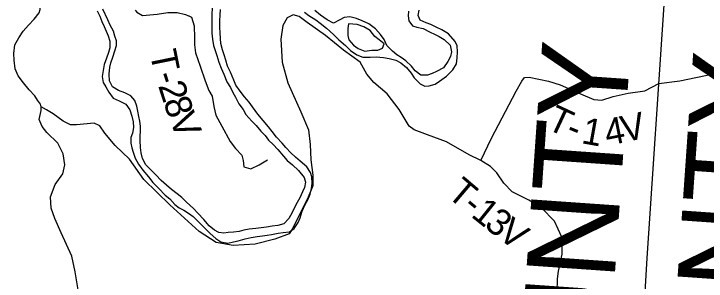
# Model space of a CAD drawing. Extents: x -15 to 405, y -40 to 87.
# Drawn here: x 26.119 to 27.6, y -28.766 to -28.194 of the extents above; entities that cross this region are included whole.
import ezdxf

# ---------------------------------------------------------------- set-up
doc = ezdxf.new("R2010")
doc.units = 0
for name, color, linetype in [('GM_P_State_Alignment', 7, 'Continuous'), ('GM_P_State_Location', 7, 'Continuous'), ('GM_X_Minor_River', 7, 'Continuous'), ('GM_X_Rail_Line', 7, 'Continuous'), ('GM_X_Township_Road', 7, 'Continuous'), ('GM_X_Township_Text', 7, 'Continuous')]:
    doc.layers.add(name, color=color, linetype=linetype)

msp = doc.modelspace()

# ---------------------------------------------------------------- linework, layer by layer
at = {"layer": 'GM_P_State_Location'}
for points in [[(26.3783, -28.1861), (26.3821, -28.1901), (26.394, -28.1971), (26.4255, -28.1944), (26.4482, -28.1908), (26.4683, -28.1911), (26.4863, -28.1956), (26.4927, -28.1984)], [(27.2809, -28.7893), (27.2815, -28.7612), (27.2838, -28.7445), (27.292, -28.7085), (27.2911, -28.6721), (27.2751, -28.6373), (27.2473, -28.6093), (27.2207, -28.5927), (27.185, -28.5749), (27.1668, -28.556), (27.1523, -28.5344), (27.1382, -28.5208), (27.1177, -28.5076), (27.0927, -28.4959), (27.044, -28.468), (27.0038, -28.4525), (26.9754, -28.4424), (26.9643, -28.4341), (26.943, -28.3985), (26.9175, -28.3648), (26.889, -28.3406), (26.8741, -28.3228), (26.86, -28.2975), (26.8239, -28.2714), (26.7852, -28.24), (26.7464, -28.2121), (26.7293, -28.1996), (26.7164, -28.1958), (26.7036, -28.2027), (26.6941, -28.2186), (26.6901, -28.2478), (26.6925, -28.2971), (26.7048, -28.3418), (26.7327, -28.4039), (26.7495, -28.4422), (26.753, -28.4736), (26.7542, -28.5062), (26.7585, -28.5392), (26.7586, -28.562), (26.7484, -28.5862), (26.7157, -28.6527), (26.7078, -28.6648), (26.6775, -28.6759), (26.6354, -28.687), (26.5881, -28.6898), (26.5517, -28.6834), (26.5156, -28.6596), (26.4525, -28.6025), (26.3973, -28.5484), (26.3661, -28.5049), (26.3357, -28.4754), (26.3136, -28.4493), (26.3029, -28.4334), (26.2908, -28.4278), (26.2529, -28.4313), (26.24, -28.4317), (26.2245, -28.4234), (26.2028, -28.4075), (26.1891, -28.3992), (26.1777, -28.3928)], [(26.4927, -28.1984), (26.4929, -28.1985), (26.4986, -28.201), (26.5048, -28.2198), (26.505, -28.2453), (26.505, -28.2605), (26.5073, -28.2771), (26.5172, -28.3061), (26.5282, -28.3374), (26.5359, -28.3577), (26.5431, -28.3701), (26.547, -28.3924), (26.5513, -28.4105), (26.564, -28.4345), (26.5819, -28.4668), (26.5933, -28.4817), (26.6066, -28.4966), (26.6091, -28.5075), (26.6106, -28.5216), (26.6259, -28.5254), (26.644, -28.5169), (26.6612, -28.5066)], [(27.4986, -28.3432), (27.5435, -28.3374), (27.6152, -28.3221), (27.7235, -28.324), (27.7512, -28.341), (27.7998, -28.3471), (27.8689, -28.3524), (27.9475, -28.3459), (27.9863, -28.3405)], [(27.1177, -28.5076), (27.1407, -28.4602), (27.1934, -28.3596), (27.2054, -28.3383), (27.2115, -28.3299), (27.221, -28.3292), (27.2623, -28.3382), (27.2877, -28.3457), (27.331, -28.3653), (27.3595, -28.377), (27.3765, -28.3788), (27.4008, -28.3708), (27.4326, -28.3639), (27.4686, -28.3589), (27.4986, -28.3432)]]:
    msp.add_lwpolyline(points, dxfattribs=at)
at = {"layer": 'GM_X_Rail_Line'}
for p, q in [((27.4737, -28.7166), (27.5098, -28.1749)), ((27.4349, -29.3708), (27.4737, -28.7166))]:
    msp.add_line(p, q, dxfattribs=at)
at = {"layer": 'GM_X_Township_Road'}
for points in [[(26.2969, -28.1874), (26.3026, -28.1988), (26.3075, -28.2102), (26.3124, -28.2212), (26.3162, -28.2311), (26.3204, -28.241), (26.3245, -28.2527), (26.3241, -28.2668), (26.3211, -28.2763), (26.3173, -28.2884), (26.3123, -28.3024), (26.3097, -28.3153), (26.3081, -28.3279), (26.31, -28.3408), (26.3157, -28.3503), (26.3221, -28.3616), (26.3312, -28.3742), (26.3441, -28.3803), (26.3582, -28.3871), (26.3673, -28.3996), (26.3711, -28.4125), (26.3741, -28.4247), (26.3752, -28.4372), (26.3729, -28.449), (26.3691, -28.4585), (26.3695, -28.4706), (26.3714, -28.4805), (26.374, -28.49), (26.3786, -28.5025), (26.3858, -28.5158), (26.3945, -28.5287), (26.407, -28.5424), (26.4165, -28.5549), (26.4294, -28.5674), (26.4423, -28.5822), (26.4525, -28.5898), (26.4631, -28.6016), (26.4726, -28.6088), (26.4825, -28.6138), (26.4927, -28.6206), (26.5022, -28.6274), (26.5144, -28.64), (26.5269, -28.6521), (26.539, -28.6639), (26.5512, -28.6745), (26.5618, -28.6817), (26.5766, -28.6844), (26.5891, -28.6818), (26.5986, -28.6795), (26.6138, -28.675), (26.6267, -28.6727), (26.6396, -28.6704), (26.6507, -28.6689), (26.6605, -28.6674), (26.67, -28.6659), (26.6841, -28.6629), (26.6947, -28.6617), (26.7084, -28.6602), (26.7186, -28.653), (26.727, -28.6401), (26.7312, -28.6303), (26.7358, -28.6162), (26.7411, -28.6033), (26.7479, -28.5919), (26.7525, -28.5794), (26.7556, -28.5677)], [(26.7275, -28.5289), (26.74, -28.5441), (26.743, -28.554), (26.7404, -28.5654), (26.7366, -28.5749), (26.7309, -28.5874), (26.7248, -28.5976), (26.7191, -28.6086), (26.7141, -28.6192), (26.7073, -28.6318), (26.6962, -28.6435), (26.6837, -28.6465), (26.6712, -28.6481), (26.659, -28.6503), (26.648, -28.6515), (26.6362, -28.653), (26.6226, -28.6548), (26.6108, -28.6571), (26.6009, -28.6594), (26.5888, -28.6609), (26.5774, -28.662), (26.5679, -28.6632), (26.5576, -28.6616), (26.5478, -28.6571), (26.5368, -28.6472), (26.525, -28.6339), (26.5125, -28.6202), (26.5034, -28.6107), (26.4886, -28.5967), (26.478, -28.5872), (26.4681, -28.5792), (26.456, -28.5701), (26.4453, -28.5602), (26.4343, -28.5503), (26.423, -28.5386), (26.4131, -28.5291), (26.401, -28.5169), (26.3941, -28.5033), (26.3911, -28.4915), (26.39, -28.4797), (26.3892, -28.4649), (26.3892, -28.4554), (26.3896, -28.4452), (26.3896, -28.4342), (26.3885, -28.4239), (26.3866, -28.4137), (26.3844, -28.4023), (26.3821, -28.3917), (26.3776, -28.3795), (26.3692, -28.3693), (26.3567, -28.3632), (26.343, -28.3582), (26.3301, -28.3499), (26.3237, -28.337), (26.3226, -28.3229), (26.3241, -28.3081), (26.3264, -28.2987), (26.3306, -28.2865), (26.3348, -28.2732), (26.3386, -28.2615), (26.3382, -28.2516), (26.3352, -28.2414), (26.3318, -28.2311), (26.3249, -28.2182), (26.32, -28.2068), (26.3094, -28.184)], [(26.5433, -28.1819), (26.5425, -28.1945), (26.5422, -28.2047), (26.5421, -28.2354), (26.5436, -28.2483), (26.5463, -28.2613), (26.5497, -28.2726), (26.5531, -28.2833), (26.5572, -28.2973), (26.5625, -28.3098), (26.5679, -28.3231), (26.5747, -28.3395), (26.5823, -28.3516), (26.5872, -28.3619), (26.5929, -28.3725), (26.6004, -28.3865), (26.6092, -28.3983), (26.6152, -28.4093), (26.6281, -28.4234), (26.6372, -28.4329), (26.6471, -28.445), (26.6566, -28.4541), (26.6634, -28.4644), (26.6736, -28.4735), (26.6835, -28.4841), (26.6956, -28.4986), (26.7036, -28.508), (26.715, -28.5172), (26.7275, -28.5289)], [(26.7556, -28.5677), (26.7567, -28.5563), (26.756, -28.543), (26.7537, -28.5335), (26.7457, -28.5214), (26.7313, -28.5092), (26.7211, -28.5008), (26.7116, -28.4914), (26.7006, -28.48), (26.693, -28.4705), (26.6809, -28.4579), (26.6714, -28.4458), (26.6638, -28.4355), (26.6524, -28.4222), (26.641, -28.4086), (26.6297, -28.393), (26.6225, -28.3831), (26.6122, -28.3714), (26.6031, -28.3596), (26.594, -28.3463), (26.5895, -28.3357), (26.5823, -28.319), (26.5762, -28.3061), (26.5721, -28.2928), (26.569, -28.2818), (26.5649, -28.2708), (26.5618, -28.2571), (26.5607, -28.2465), (26.56, -28.2343), (26.5596, -28.2229), (26.5596, -28.2078), (26.56, -28.1964), (26.5612, -28.1846)], [(26.7408, -28.1901), (26.7502, -28.1973), (26.7647, -28.2064), (26.7741, -28.2136), (26.7874, -28.2246), (26.803, -28.2379), (26.814, -28.2497), (26.8284, -28.2618), (26.839, -28.2725), (26.8523, -28.2816), (26.8656, -28.2865), (26.8808, -28.2866), (26.8937, -28.2862), (26.9096, -28.287), (26.9214, -28.2892), (26.9358, -28.293), (26.9465, -28.2984), (26.959, -28.3086), (26.9685, -28.3208), (26.9749, -28.3306), (26.9878, -28.3436), (26.9977, -28.3485), (27.0072, -28.3481), (27.0201, -28.3443), (27.0296, -28.3379), (27.044, -28.3269), (27.0577, -28.314), (27.0657, -28.3011), (27.0668, -28.2878), (27.068, -28.2753), (27.0669, -28.2624), (27.0631, -28.2529), (27.0487, -28.2366), (27.0346, -28.2282), (27.0225, -28.2221), (27.0107, -28.2168), (27.0008, -28.2134), (26.9879, -28.2077), (26.9838, -28.1975), (26.9857, -28.1857)], [(26.9629, -28.1883), (26.9625, -28.1982), (26.964, -28.2092), (26.9716, -28.2198), (26.9811, -28.2221), (26.9947, -28.2255), (27.0096, -28.2331), (27.019, -28.2377), (27.0289, -28.2426), (27.0395, -28.2487), (27.052, -28.2609), (27.0551, -28.2753), (27.0532, -28.2852), (27.0475, -28.2962), (27.038, -28.3091), (27.0231, -28.3174), (27.0136, -28.3219), (27.0038, -28.3254), (26.9893, -28.325), (26.9772, -28.3158), (26.9696, -28.306), (26.9571, -28.2942), (26.9476, -28.2874), (26.9381, -28.2813), (26.9286, -28.2741), (26.9169, -28.2615), (26.9108, -28.2486), (26.9032, -28.2384), (26.8926, -28.2262), (26.8782, -28.2156), (26.8641, -28.2087), (26.852, -28.2038), (26.8376, -28.2004), (26.8258, -28.2019), (26.8163, -28.2068), (26.8026, -28.2136), (26.789, -28.2068), (26.7745, -28.1965), (26.7628, -28.1867)], [(26.8344, -28.2152), (26.8333, -28.2254), (26.8333, -28.2402), (26.8356, -28.2497), (26.8455, -28.2607), (26.8557, -28.2682), (26.8697, -28.2739), (26.8845, -28.2716), (26.8974, -28.2716), (26.9025, -28.2694)], [(26.9025, -28.2694), (26.9072, -28.2674), (26.911, -28.2579), (26.9004, -28.2492), (26.8909, -28.2424), (26.881, -28.2295), (26.8678, -28.2219), (26.8534, -28.2167), (26.8344, -28.2152)]]:
    msp.add_lwpolyline(points, dxfattribs=at)
at = {"layer": 'GM_X_Township_Text'}
for points in [[(26.1393, -28.3413), (26.1279, -28.3266), (26.1217, -28.3118), (26.1198, -28.2928), (26.119, -28.2784), (26.1212, -28.2602), (26.1295, -28.245), (26.1389, -28.231), (26.1502, -28.2181), (26.1627, -28.2055), (26.1729, -28.1919), (26.175, -28.1844), (26.175, -28.1817)], [(26.1777, -28.3928), (26.1758, -28.3871), (26.1699, -28.3785), (26.1636, -28.3693), (26.1515, -28.3568), (26.1393, -28.3413)], [(26.2564, -28.7846), (26.2498, -28.7463), (26.2429, -28.7122), (26.22, -28.6626), (26.2066, -28.6316), (26.1989, -28.6096), (26.1973, -28.5853), (26.2071, -28.5588), (26.2237, -28.5364), (26.2278, -28.517), (26.2247, -28.4935), (26.2132, -28.4708), (26.1893, -28.4477), (26.1798, -28.4349), (26.1733, -28.4201), (26.1774, -28.4004), (26.1777, -28.3928)]]:
    msp.add_lwpolyline(points, dxfattribs=at)

# ---------------------------------------------------------------- texts
at = {"layer": 'GM_P_State_Alignment'}
for s, p in [('VINTON  COUNTY', (27.2881, -30.4223)), ('MEIGS  COUNTY', (27.6206, -30.3058))]:
    msp.add_text(s, height=0.189394, rotation=86.0177, dxfattribs=at).set_placement(p)
at = {"layer": 'GM_X_Minor_River'}
for s, rotation, p in [('T', 281.5293, (26.4095, -28.2767)), ('-', 288.1676, (26.4198, -28.3253)), ('2', 287.9544, (26.4271, -28.3474)), ('8', 288.2807, (26.438, -28.381)), ('V', 291.9877, (26.4503, -28.418)), ('T', 335.0336, (27.2556, -28.4386)), ('4', 11.0329, (27.3881, -28.4764)), ('V', 12.3806, (27.4239, -28.4694)), ('1', 349.8632, (27.3309, -28.4704)), ('-', 337.375, (27.2964, -28.4576)), ('T', 319.6479, (27.043, -28.583)), ('-', 320.144, (27.0758, -28.6108)), ('1', 321.137, (27.0946, -28.6264)), ('3', 322.0707, (27.1226, -28.649)), ('V', 323.3424, (27.1513, -28.6714))]:
    msp.add_text(s, height=0.0568, rotation=rotation, dxfattribs=at).set_placement(p)

doc.saveas('drawing.dxf')
